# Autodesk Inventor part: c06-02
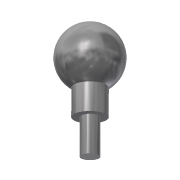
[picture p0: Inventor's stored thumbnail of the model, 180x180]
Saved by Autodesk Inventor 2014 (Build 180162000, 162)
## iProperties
Created: 2013-03
Part Number: c06-02
Material: Steel, Carbon
Document SubType Name: Modeling
Designer: Thom Tremblay
Density: 7.87 g/cm^3
Appearance: Semi-Polished
Author: Thom Tremblay
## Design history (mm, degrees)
sketch "Sketch1"
  geometry: C1 r 9 at (0, 0); 1 further point
  constraints: 1 centre point, 1 coincident
  dimensions: "d0" = 18 diameter of C1
extrude "Extrusion1" new body sketch "Sketch1" distance "d1" = 30; taper "d2" = 0 deg
sketch "Sketch2"
  geometry: C1 r 9 at (0, 0) reference; C2 r 5 at (0, 0)
  constraints: 1 centre point, 1 coincident
  dimensions: "d3" = 10 diameter of C2
extrude "Extrusion2" join sketch "Sketch2" distance "d4" = 20; taper "d5" = 0 deg
sketch "Sketch3"
  geometry: L1 (16.121, 6.81)-(-16.121, -6.81); C1 r 9 at (0, 0) reference; A1 r 17.5 centre (0, 0) between (16.121, 6.81) and (-16.121, -6.81)
  constraints: 2 end point, 2 point on circle, 1 centre point, 1 coincident, 1 midpoint
  dimensions: "d6" = 35 diameter of A1
revolve "Revolution1" sketch "Sketch3" stored, may be unused: angle "d7" = 90 deg
body "Solid1"
